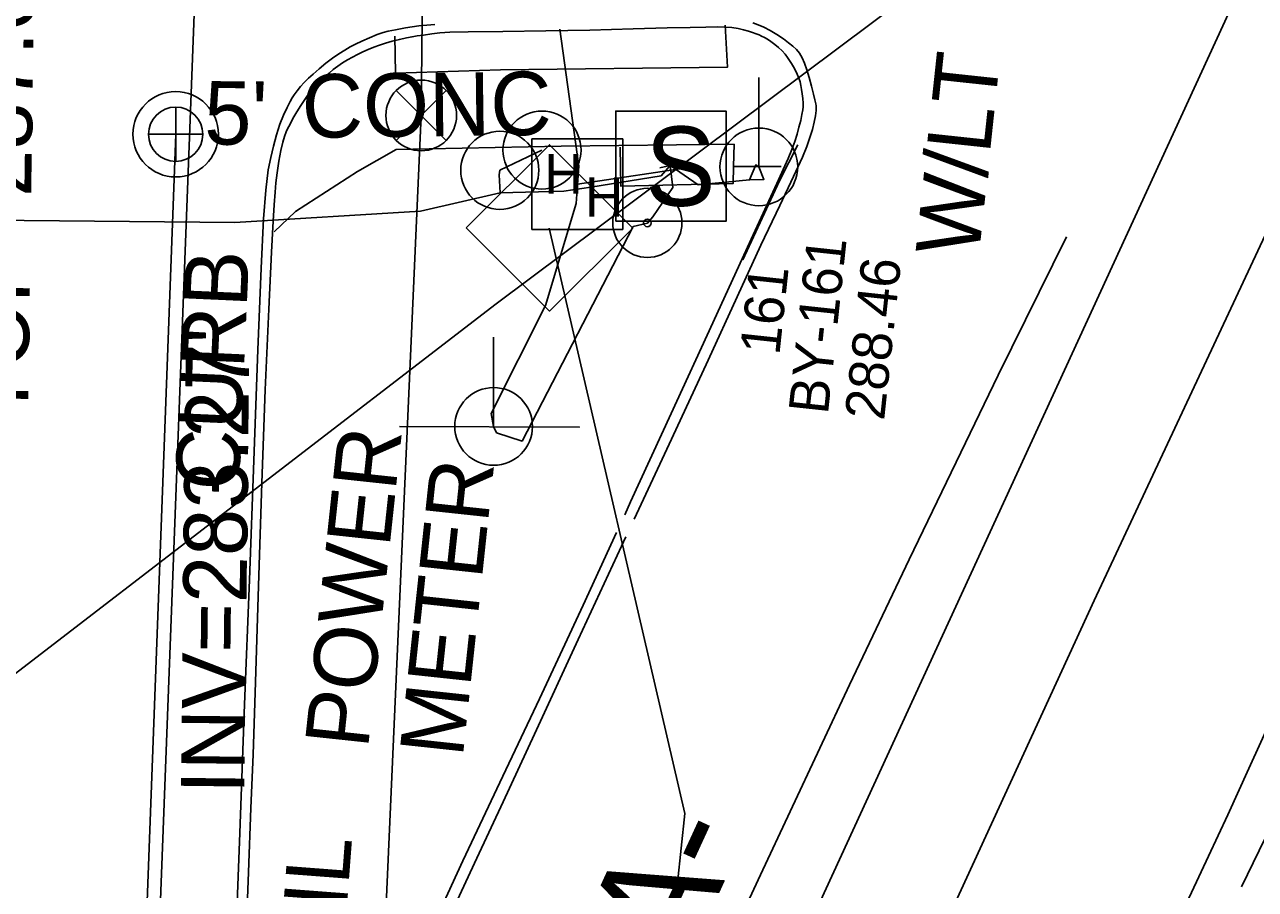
# Model space of a CAD drawing. Extents: x 2100323 to 2109811, y 740376 to 749755.
# Drawn here: x 2105116.4 to 2105194, y 742071.5 to 742126 of the extents above; entities that cross this region are included whole.
import ezdxf

# ---------------------------------------------------------------- set-up
doc = ezdxf.new("R2010")
doc.units = 0
for name, color, linetype in [('CTL Supplemental Horizontal and Vertical CELL', 7, 'Continuous'), ('CTL Supplemental Horizontal and Vertical Cogo Comment', 7, 'Continuous'), ('CTL Supplemental Horizontal and Vertical Cogo Elevation', 7, 'Continuous'), ('CTL Supplemental Horizontal and Vertical Cogo Number', 7, 'Continuous'), ('Exist Horizontal Alignment', 7, 'Continuous'), ('Exist Horizontal Alignment Direction Label', 7, 'Continuous'), ('Exist Horizontal Baseline Alignment Station Label', 7, 'Continuous'), ('Exist Other Culture Area Outline', 7, 'Continuous'), ('Exist Roads Curbs', 7, 'Continuous'), ('Exist Roads Curbs Text', 7, 'Continuous'), ('Exist Roads EOP', 7, 'Continuous'), ('Exist Roads EOP Other', 7, 'Continuous'), ('Exist Roads EOP Other Text', 7, 'Continuous'), ('Exist Roads EOT', 7, 'Continuous'), ('Exist Utilities Other Located Object CELL', 7, 'Continuous'), ('Exist Utilities Other Located Object Text', 7, 'Continuous'), ('Exist Utilities Other Pole CELL', 7, 'Continuous'), ('Exist Utilities Other Pole Located Topo Text', 7, 'Continuous'), ('Exist Utilities Other Traffic Signal Box CELL', 7, 'Continuous'), ('Exist Utilities Power Joint Use Telephone CELL', 7, 'Continuous'), ('Exist Utilities Power Pole CELL', 7, 'Continuous'), ('Exist Utilities Power UG Cable SUE LOS B', 7, 'Continuous'), ('Exist Utilities Sanitary Sewer Manhole CELL', 7, 'Continuous'), ('Exist Utilities Sanitary Sewer Manhole Text', 7, 'Continuous'), ('Exist Utilities Sanitary Sewer UG Line', 7, 'Continuous'), ('Exist Utilities Sanitary Sewer UG Line Invert Elevation', 7, 'Continuous'), ('Exist Utilities Telephone Hand Hole CELL', 7, 'Continuous'), ('Exist Utilities Telephone UG Conduit SUE LOS B', 7, 'Continuous'), ('Exist Utilities Water UG Line SUE LOS B', 7, 'Continuous'), ('Exist Utilities Water Valve CELL', 7, 'Continuous')]:
    doc.layers.add(name, color=color, linetype=linetype)

msp = doc.modelspace()

# ---------------------------------------------------------------- linework, layer by layer
at = {"layer": 'CTL Supplemental Horizontal and Vertical CELL'}
msp.add_line((2105149.466, 742113.192), (2105149.466, 742113.192), dxfattribs=at)
msp.add_lwpolyline([(2105144.251, 742113.21), (2105149.493, 742118.451), (2105154.743, 742113.201), (2105149.501, 742107.96)], close=True, dxfattribs=at)
at = {"layer": 'Exist Horizontal Alignment'}
for p, q in [((2105114.07, 741782.467), (2105127.955, 742149.664)), ((2105121.244, 741972.172), (2105202.941, 742149.867))]:
    msp.add_line(p, q, dxfattribs=at)
at = {"layer": 'Exist Horizontal Baseline Alignment Station Label'}
for p, q in [((2105149.466, 742113.192), (2105158.033, 742076.269)), ((2105158.033, 742076.269), (2105153.379, 742032.816))]:
    msp.add_line(p, q, dxfattribs=at)
at = {"layer": 'Exist Other Culture Area Outline'}
msp.add_lwpolyline([(2105161.103, 742117.082), (2105161.075, 742116), (2105153.994, 742115.835), (2105153.961, 742118.294)], dxfattribs=at)
at = {"layer": 'Exist Roads Curbs'}
for points in [[(2105130.335, 742067.596), (2105130.506, 742072.573), (2105130.66, 742076.602), (2105130.802, 742079.988), (2105130.962, 742084.563), (2105131.147, 742090.633), (2105131.352, 742097.131), (2105131.572, 742102.989), (2105131.796, 742108.084), (2105131.966, 742111.673), (2105132.072, 742113.633), (2105132.14, 742114.66), (2105132.194, 742115.452), (2105132.241, 742116.048), (2105132.319, 742116.688), (2105132.432, 742117.411), (2105132.559, 742118.093), (2105132.678, 742118.606), (2105132.789, 742118.966), (2105132.896, 742119.256), (2105133.002, 742119.492), (2105133.113, 742119.71), (2105133.238, 742119.946), (2105133.381, 742120.206), (2105133.572, 742120.53), (2105133.818, 742120.926), (2105134.071, 742121.314), (2105134.286, 742121.617), (2105134.475, 742121.849), (2105134.71, 742122.107), (2105135.003, 742122.407), (2105135.313, 742122.708), (2105135.598, 742122.972), (2105135.865, 742123.202), (2105136.145, 742123.416), (2105136.443, 742123.618), (2105136.753, 742123.807), (2105137.071, 742123.983), (2105137.395, 742124.147), (2105137.727, 742124.304), (2105138.066, 742124.456), (2105138.416, 742124.601), (2105138.779, 742124.734), (2105139.158, 742124.858), (2105139.574, 742124.977), (2105140.031, 742125.093), (2105140.47, 742125.193), (2105140.834, 742125.265), (2105141.146, 742125.313), (2105141.551, 742125.37), (2105142.075, 742125.441), (2105142.573, 742125.505), (2105142.899, 742125.54), (2105143.202, 742125.552), (2105144.372, 742125.567), (2105146.557, 742125.589), (2105149.274, 742125.626), (2105152.042, 742125.686), (2105154.768, 742125.761), (2105156.906, 742125.82), (2105158.364, 742125.856), (2105159.351, 742125.875), (2105160.077, 742125.882), (2105160.569, 742125.876), (2105160.995, 742125.842), (2105161.383, 742125.778), (2105161.731, 742125.698), (2105162.037, 742125.616), (2105162.3, 742125.532), (2105162.523, 742125.454), (2105162.705, 742125.383), (2105162.872, 742125.308), (2105163.05, 742125.217), (2105163.242, 742125.108), (2105163.457, 742124.964), (2105163.697, 742124.782), (2105163.938, 742124.579), (2105164.155, 742124.369), (2105164.348, 742124.156), (2105164.508, 742123.954), (2105164.636, 742123.768), (2105164.751, 742123.579), (2105164.874, 742123.368), (2105165.003, 742123.137), (2105165.117, 742122.9), (2105165.214, 742122.659), (2105165.293, 742122.418), (2105165.35, 742122.18), (2105165.389, 742121.939), (2105165.425, 742121.668), (2105165.462, 742121.362), (2105165.488, 742121.069), (2105165.49, 742120.837), (2105165.467, 742120.645), (2105165.415, 742120.37), (2105165.333, 742119.991), (2105165.226, 742119.557), (2105165.101, 742119.118), (2105164.955, 742118.667), (2105164.77, 742118.159), (2105164.543, 742117.588), (2105163.838, 742116.011), (2105162.221, 742112.487), (2105159.793, 742107.229), (2105157.164, 742101.512), (2105154.61, 742095.932), (2105154.236, 742095.115)], [(2105161.676, 742111.189), (2105164.002, 742116.176), (2105165.155, 742118.441)], [(2105153.721, 742093.987), (2105151.611, 742089.405), (2105148.857, 742083.503), (2105146.357, 742078.228), (2105144.025, 742073.29), (2105141.774, 742068.401)]]:
    msp.add_lwpolyline(points, dxfattribs=at)
at = {"layer": 'Exist Roads EOP'}
for points in [[(2105154.84, 742094.838), (2105157.195, 742099.878), (2105159.497, 742104.857), (2105161.329, 742108.867), (2105162.827, 742112.111), (2105164.014, 742114.623), (2105164.887, 742116.458), (2105165.443, 742117.673), (2105165.717, 742118.342), (2105165.914, 742118.899), (2105166.068, 742119.418), (2105166.183, 742119.882), (2105166.26, 742120.279), (2105166.3, 742120.612), (2105166.299, 742120.901), (2105166.283, 742121.031), (2105166.222, 742121.282), (2105166.131, 742121.65), (2105166.012, 742122.157), (2105165.874, 742122.7), (2105165.729, 742123.18), (2105165.577, 742123.595), (2105165.416, 742123.943), (2105165.248, 742124.222), (2105165.059, 742124.459), (2105164.836, 742124.678), (2105164.574, 742124.886), (2105164.24, 742125.123), (2105163.828, 742125.397), (2105163.398, 742125.661), (2105163.007, 742125.868), (2105162.653, 742126.022), (2105162.326, 742126.151)], [(2105142.255, 742126.032), (2105141.248, 742125.945), (2105140.426, 742125.827), (2105139.785, 742125.706), (2105139.325, 742125.61), (2105139.01, 742125.527), (2105138.631, 742125.395), (2105138.153, 742125.201), (2105137.668, 742124.987), (2105137.267, 742124.795), (2105136.937, 742124.617), (2105136.589, 742124.415), (2105136.209, 742124.183), (2105135.806, 742123.911), (2105135.386, 742123.59), (2105134.962, 742123.232), (2105134.594, 742122.911), (2105134.293, 742122.641), (2105134.036, 742122.388), (2105133.796, 742122.12), (2105133.579, 742121.843), (2105133.405, 742121.604), (2105133.277, 742121.408), (2105133.144, 742121.171), (2105132.954, 742120.807), (2105132.717, 742120.321), (2105132.491, 742119.743), (2105132.285, 742119.078), (2105132.097, 742118.368), (2105131.924, 742117.652), (2105131.765, 742116.865), (2105131.615, 742115.596), (2105131.471, 742113.779), (2105131.308, 742110.667), (2105131.098, 742105.513), (2105130.846, 742098.533), (2105130.569, 742091.011), (2105130.271, 742083.159), (2105129.963, 742075.061), (2105129.653, 742066.796)], [(2105143.12, 742069.606), (2105144.914, 742073.465), (2105146.571, 742077.02), (2105148.55, 742081.278), (2105151.307, 742087.243), (2105154.316, 742093.715)], [(2105195.1, 742082.43), (2105193.599, 742079.111), (2105192.261, 742076.186), (2105191.054, 742073.583), (2105189.972, 742071.292), (2105188.869, 742068.964), (2105187.598, 742066.249), (2105186.133, 742063.094), (2105184.323, 742059.185), (2105182.142, 742054.469), (2105179.615, 742048.996), (2105176.768, 742042.817), (2105173.698, 742036.133), (2105170.991, 742030.147), (2105168.744, 742025.059), (2105166.957, 742020.929), (2105165.629, 742017.817), (2105164.71, 742015.61), (2105163.916, 742013.628), (2105163.2, 742011.758), (2105162.495, 742009.812), (2105161.739, 742007.605), (2105160.912, 742005.087), (2105159.909, 742001.961)]]:
    msp.add_lwpolyline(points, dxfattribs=at)
at = {"layer": 'Exist Roads EOP Other'}
for points in [[(2105160.575, 742125.992), (2105160.723, 742123.347), (2105146.41, 742123.167), (2105139.781, 742122.965), (2105139.742, 742125.29)], [(2105164.096, 742117.07), (2105161.103, 742117.082), (2105161.136, 742118.484), (2105150.233, 742118.355), (2105139.822, 742118.155), (2105137.38, 742116.757), (2105133.474, 742114.237), (2105132.138, 742112.959)], [(2105200.85, 742087.988), (2105197.177, 742080), (2105193.135, 742071.654)]]:
    msp.add_lwpolyline(points, dxfattribs=at)
at = {"layer": 'Exist Roads EOT'}
for points in [[(2105182.093, 742112.636), (2105177.783, 742103.921), (2105172.174, 742092.295), (2105168.421, 742084.389), (2105162.799, 742072.415), (2105156.586, 742059.006), (2105151.308, 742047.303), (2105145.911, 742034.869), (2105141.71, 742024.904), (2105137.709, 742015.074), (2105134.028, 742005.078), (2105131.587, 741998.064), (2105129.533, 741992.045), (2105127.985, 741986.696)], [(2105140.512, 741984.365), (2105147.179, 742006.888), (2105155.072, 742026.428), (2105166.228, 742052.345), (2105174.607, 742069.641), (2105183.843, 742089.711), (2105194.629, 742112.742)]]:
    msp.add_lwpolyline(points, dxfattribs=at)
at = {"layer": 'Exist Utilities Other Located Object CELL'}
for radius in [2.18, 0.24]:
    msp.add_circle((2105155.667, 742113.525), radius, dxfattribs=at)
at = {"layer": 'Exist Utilities Other Pole CELL'}
for centre in [(2105149.022, 742118.116), (2105146.361, 742116.84)]:
    msp.add_circle(centre, 2.463, dxfattribs=at)
at = {"layer": 'Exist Utilities Other Traffic Signal Box CELL'}
msp.add_line((2105157.151, 742117.1), (2105157.151, 742117.1), dxfattribs=at)
msp.add_lwpolyline([(2105153.676, 742113.625), (2105160.626, 742113.625), (2105160.626, 742120.575), (2105153.676, 742120.575), (2105153.676, 742113.625)], dxfattribs=at)
at = {"layer": 'Exist Utilities Power Joint Use Telephone CELL'}
msp.add_line((2105145.971, 742100.681), (2105145.971, 742100.681), dxfattribs=at)
msp.add_lwpolyline([(2105140.033, 742100.681), (2105151.371, 742100.644), (2105145.971, 742100.662), (2105145.971, 742106.306)], dxfattribs=at)
msp.add_circle((2105145.972, 742100.688), 2.45, dxfattribs=at)
at = {"layer": 'Exist Utilities Power Pole CELL'}
for q in [(2105162.695, 742122.683), (2105162.695, 742117.058)]:
    msp.add_line((2105162.695, 742117.058), q, dxfattribs=at)
msp.add_circle((2105162.695, 742117.058), 2.45, dxfattribs=at)
at = {"layer": 'Exist Utilities Power UG Cable SUE LOS B'}
for p, q in [((2105146.361, 742116.841), (2105149.022, 742118.116)), ((2105146.329, 742116.556), (2105146.361, 742116.841)), ((2105157.112, 742117.151), (2105157.274, 742115.766)), ((2105150.409, 742115.532), (2105146.391, 742115.417)), ((2105157.274, 742115.766), (2105156.003, 742113.903))]:
    msp.add_line(p, q, dxfattribs=at)
for points in [[(2105145.81, 742101.497), (2105149.242, 742108.303), (2105151.176, 742114.743), (2105151.34, 742117.108), (2105150.157, 742125.735)], [(2105156.543, 742116.49), (2105157.112, 742117.151), (2105158.864, 742115.931), (2105162.108, 742116.231), (2105162.499, 742117.177), (2105162.694, 742117.058), (2105163.019, 742116.268), (2105162.108, 742116.231)], [(2105141.351, 742114.259), (2105146.391, 742115.417), (2105146.329, 742116.556)], [(2105150.409, 742115.532), (2105152.104, 742115.783), (2105156.543, 742116.49)], [(2105092.549, 742113.98), (2105100.74, 742113.612), (2105114.138, 742113.705), (2105129.651, 742113.554), (2105141.351, 742114.259)], [(2105156.003, 742113.903), (2105155.675, 742113.515), (2105154.778, 742113.289)], [(2105154.778, 742113.289), (2105147.762, 742099.765), (2105146.154, 742100.278)], [(2105146.154, 742100.278), (2105145.971, 742100.682), (2105145.81, 742101.497)]]:
    msp.add_lwpolyline(points, dxfattribs=at)
at = {"layer": 'Exist Utilities Sanitary Sewer Manhole CELL'}
msp.add_lwpolyline([(2105125.925, 742120.827), (2105125.925, 742117.402), (2105125.925, 742119.115), (2105127.637, 742119.115), (2105124.212, 742119.115)], dxfattribs=at)
for radius in [2.694, 1.712]:
    msp.add_circle((2105125.925, 742119.115), radius, dxfattribs=at)
at = {"layer": 'Exist Utilities Sanitary Sewer UG Line'}
msp.add_lwpolyline([(2105125.925, 742119.115), (2105107.923, 741637.482)], dxfattribs=at)
at = {"layer": 'Exist Utilities Telephone Hand Hole CELL'}
for p, q in [((2105148.391, 742118.826), (2105148.391, 742113.101)), ((2105154.115, 742118.826), (2105148.391, 742118.826)), ((2105154.115, 742113.101), (2105154.115, 742118.826)), ((2105151.253, 742115.964), (2105151.253, 742115.964)), ((2105148.391, 742113.101), (2105154.115, 742113.101))]:
    msp.add_line(p, q, dxfattribs=at)
at = {"layer": 'Exist Utilities Telephone UG Conduit SUE LOS B'}
for p, q in [((2105158.844, 742117.103), (2105151.253, 742115.964)), ((2105157.112, 742117.151), (2105156.457, 742117.005))]:
    msp.add_line(p, q, dxfattribs=at)
msp.add_lwpolyline([(2105103.131, 742088.495), (2105101.009, 742072.786), (2105111.685, 742081.926), (2105146.141, 742108.414), (2105186.571, 742138.69), (2105209.148, 742157.951), (2105240.685, 742192.748), (2105255.444, 742191.892), (2105405.101, 742191.496), (2105465.373, 742191.697), (2105498.782, 742193.465), (2105569.455, 742194.912), (2105579.793, 742194.992), (2105583.832, 742193.798), (2105587.319, 742190.308), (2105620.453, 742190.951), (2105664.049, 742170.377), (2105679.452, 742164.298), (2105754.897, 742133.713), (2105860.555, 742098.34), (2105944.571, 742073.094)], dxfattribs=at)
at = {"layer": 'Exist Utilities Water UG Line SUE LOS B'}
msp.add_lwpolyline([(2105121.485, 741679.881), (2105122.261, 741701.679), (2105123.534, 741730.099), (2105127.235, 741791.303), (2105130.345, 741851.732), (2105134.568, 741956.374), (2105137.545, 742033.083), (2105141.408, 742120.3), (2105141.648, 742144.896), (2105141.764, 742148.567), (2105142.227, 742156.512), (2105142.292, 742165.064)], dxfattribs=at)
at = {"layer": 'Exist Utilities Water Valve CELL'}
msp.add_lwpolyline([(2105142.983, 742121.875), (2105139.833, 742118.725), (2105141.408, 742120.3), (2105142.983, 742118.725), (2105139.833, 742121.875)], dxfattribs=at)
msp.add_circle((2105141.408, 742120.3), 2.227, dxfattribs=at)

# ---------------------------------------------------------------- texts
at = {"layer": 'CTL Supplemental Horizontal and Vertical Cogo Comment'}
msp.add_text('BY-161', height=2.5, rotation=83.88645, dxfattribs=at).set_placement((2105167.047, 742101.394))
at = {"layer": 'CTL Supplemental Horizontal and Vertical Cogo Elevation'}
msp.add_text('288.46', height=2.5, rotation=83.88645, dxfattribs=at).set_placement((2105170.589, 742101.018))
at = {"layer": 'CTL Supplemental Horizontal and Vertical Cogo Number'}
msp.add_text('161', height=2.5, rotation=83.88645, dxfattribs=at).set_placement((2105163.986, 742105.133))
at = {"layer": 'Exist Horizontal Alignment Direction Label'}
msp.add_text('-EY3A-', height=7, rotation=65.30889, dxfattribs=at).set_placement((2105149.273, 742047.501))
at = {"layer": 'Exist Roads Curbs Text'}
msp.add_text('CURB', height=4, rotation=87.42523, dxfattribs=at).set_placement((2105129.883, 742096.574))
at = {"layer": 'Exist Roads EOP Other Text'}
for s, rotation, p in [('CONC', 0.72279, (2105133.896, 742118.883)), ("5'", 359.55033, (2105127.716, 742118.47)), ('SOIL', 85.65529, (2105136.124, 742062.537))]:
    msp.add_text(s, height=4, rotation=rotation, dxfattribs=at).set_placement(p)
at = {"layer": 'Exist Utilities Other Located Object Text'}
for s, p in [('POWER', (2105138.046, 742080.303)), ('METER', (2105144.022, 742079.757))]:
    msp.add_text(s, height=4, rotation=83.88645, dxfattribs=at).set_placement(p)
at = {"layer": 'Exist Utilities Other Pole Located Topo Text'}
msp.add_text('W/LT', height=4, rotation=83.88645, dxfattribs=at).set_placement((2105176.557, 742111.316))
at = {"layer": 'Exist Utilities Other Traffic Signal Box CELL'}
msp.add_text('S', height=5, dxfattribs=at).set_placement((2105155.517, 742114.6))
at = {"layer": 'Exist Utilities Sanitary Sewer Manhole Text'}
msp.add_text("TOP=287.69'", height=4, rotation=89.18205, dxfattribs=at).set_placement((2105116.61, 742101.036))
at = {"layer": 'Exist Utilities Sanitary Sewer UG Line Invert Elevation'}
msp.add_text("INV=283.27'", height=4, rotation=89.35973, dxfattribs=at).set_placement((2105130.252, 742077.483))
at = {"layer": 'Exist Utilities Telephone Hand Hole CELL'}
for p in [(2105149.169, 742115.372), (2105151.741, 742113.907)]:
    msp.add_text('H', height=2.5, dxfattribs=at).set_placement(p)

doc.saveas('drawing.dxf')
